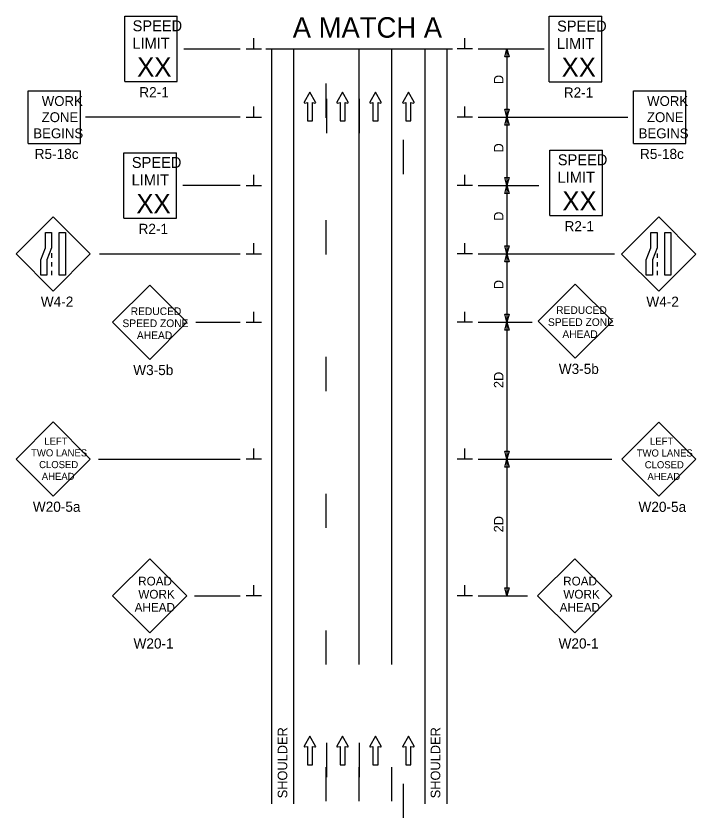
# Model space of a CAD drawing. Extents: x 16512 to 19509, y 5761 to 6974.
# Drawn here: x 17850 to 18347, y 6327 to 6913 of the extents above; entities that cross this region are included whole.
import ezdxf

# ---------------------------------------------------------------- set-up
doc = ezdxf.new("R2010")
doc.units = 0
for name, color, linetype in [('ALI_LEGAL_EX', 7, 'Continuous'), ('MT_SCRATCH_LEVEL_E', 7, 'Continuous'), ('PAVT_EDGE_EX', 7, 'Continuous'), ('TRAFFIC_SIGNS_PR', 7, 'Continuous'), ('TYPICAL_TEXT_DIMEN_PR', 7, 'Continuous')]:
    doc.layers.add(name, color=color, linetype=linetype)

msp = doc.modelspace()

# ---------------------------------------------------------------- linework, layer by layer
at = {"layer": 'ALI_LEGAL_EX'}
for p, q in [((18101.18, 6438.7), (18101.18, 6889.05)), ((18125.18, 6438.7), (18125.18, 6889.05))]:
    msp.add_line(p, q, dxfattribs=at)
for points in [[(18077.18, 6838.7), (18077.18, 6863.7)], [(18101.18, 6838.7), (18101.18, 6863.7)], [(18125.18, 6838.7), (18125.18, 6863.7)], [(18077.28, 6852.4), (18077.28, 6827.4)], [(18101.28, 6852.4), (18101.28, 6827.4)], [(18133.42, 6822.52), (18133.42, 6797.52)], [(18077.18, 6738.7), (18077.18, 6763.7)], [(18101.18, 6738.7), (18101.18, 6763.7)], [(18125.18, 6738.7), (18125.18, 6763.7)], [(18077.18, 6638.7), (18077.18, 6663.7)], [(18101.18, 6638.7), (18101.18, 6663.7)], [(18125.18, 6638.7), (18125.18, 6663.7)], [(18077.18, 6538.7), (18077.18, 6563.7)], [(18101.18, 6538.7), (18101.18, 6563.7)], [(18125.18, 6538.7), (18125.18, 6563.7)], [(18077.18, 6438.7), (18077.18, 6463.7)], [(18101.18, 6438.7), (18101.18, 6463.7)], [(18125.18, 6438.7), (18125.18, 6463.7)], [(18077.28, 6381.39), (18077.28, 6356.39)], [(18101.28, 6381.39), (18101.28, 6356.39)], [(18077.18, 6338.7), (18077.18, 6363.7)], [(18101.18, 6338.7), (18101.18, 6363.7)], [(18125.18, 6338.7), (18125.18, 6363.7)], [(18133.42, 6351.51), (18133.42, 6326.51)]]:
    msp.add_lwpolyline(points, dxfattribs=at)
at = {"layer": 'MT_SCRATCH_LEVEL_E'}
for p, q in [((18065.19, 6857.36), (18061.08, 6850.12)), ((18069.34, 6850.12), (18065.19, 6857.36)), ((18089.05, 6857.36), (18084.94, 6850.12)), ((18093.19, 6850.12), (18089.05, 6857.36)), ((18113.1, 6857.36), (18108.99, 6850.12)), ((18117.25, 6850.12), (18113.1, 6857.36)), ((18137.15, 6857.36), (18133.04, 6850.12)), ((18137.15, 6857.36), (18133.04, 6850.12)), ((18141.3, 6850.12), (18137.15, 6857.36)), ((18141.3, 6850.12), (18137.15, 6857.36)), ((18061.57, 6849.44), (18063.34, 6849.75)), ((18063.34, 6849.75), (18063.34, 6836.5)), ((18067.08, 6836.5), (18067.08, 6849.75)), ((18067.08, 6849.75), (18068.86, 6849.44)), ((18085.42, 6849.44), (18087.19, 6849.75)), ((18087.19, 6849.75), (18087.19, 6836.5)), ((18090.94, 6836.5), (18090.94, 6849.75)), ((18090.94, 6849.75), (18092.71, 6849.44)), ((18109.47, 6849.44), (18111.25, 6849.75)), ((18111.25, 6849.75), (18111.25, 6836.5)), ((18114.99, 6836.5), (18114.99, 6849.75)), ((18114.99, 6849.75), (18116.77, 6849.44)), ((18133.52, 6849.44), (18135.3, 6849.76)), ((18133.52, 6849.44), (18135.3, 6849.76)), ((18135.3, 6849.76), (18135.3, 6836.5)), ((18135.3, 6849.76), (18135.3, 6836.5)), ((18139.04, 6836.5), (18139.04, 6849.76)), ((18139.04, 6849.76), (18140.82, 6849.44)), ((18139.04, 6836.5), (18139.04, 6849.76)), ((18139.04, 6849.76), (18140.82, 6849.44)), ((18063.34, 6836.5), (18067.08, 6836.5)), ((18087.19, 6836.5), (18090.94, 6836.5)), ((18111.25, 6836.5), (18114.99, 6836.5)), ((18135.3, 6836.5), (18139.04, 6836.5)), ((18135.3, 6836.5), (18139.04, 6836.5)), ((18065.19, 6386.35), (18061.08, 6379.11)), ((18069.34, 6379.11), (18065.19, 6386.35)), ((18089.05, 6386.35), (18084.94, 6379.11)), ((18093.19, 6379.11), (18089.05, 6386.35)), ((18113.1, 6386.35), (18108.99, 6379.11)), ((18117.25, 6379.11), (18113.1, 6386.35)), ((18137.15, 6386.35), (18133.04, 6379.11)), ((18137.15, 6386.35), (18133.04, 6379.11)), ((18141.3, 6379.11), (18137.15, 6386.35)), ((18141.3, 6379.11), (18137.15, 6386.35)), ((18061.57, 6378.43), (18063.34, 6378.74)), ((18063.34, 6378.74), (18063.34, 6365.49)), ((18067.08, 6365.49), (18067.08, 6378.74)), ((18067.08, 6378.74), (18068.86, 6378.43)), ((18085.42, 6378.43), (18087.19, 6378.74)), ((18087.19, 6378.74), (18087.19, 6365.49)), ((18090.94, 6365.49), (18090.94, 6378.74)), ((18090.94, 6378.74), (18092.71, 6378.43)), ((18109.47, 6378.43), (18111.25, 6378.74)), ((18111.25, 6378.74), (18111.25, 6365.49)), ((18114.99, 6365.49), (18114.99, 6378.74)), ((18114.99, 6378.74), (18116.77, 6378.43)), ((18133.52, 6378.43), (18135.3, 6378.74)), ((18133.52, 6378.43), (18135.3, 6378.74)), ((18135.3, 6378.74), (18135.3, 6365.49)), ((18135.3, 6378.74), (18135.3, 6365.49)), ((18139.04, 6365.49), (18139.04, 6378.74)), ((18139.04, 6378.74), (18140.82, 6378.43)), ((18139.04, 6365.49), (18139.04, 6378.74)), ((18139.04, 6378.74), (18140.82, 6378.43)), ((18063.34, 6365.49), (18067.08, 6365.49)), ((18087.19, 6365.49), (18090.94, 6365.49)), ((18111.25, 6365.49), (18114.99, 6365.49)), ((18135.3, 6365.49), (18139.04, 6365.49)), ((18135.3, 6365.49), (18139.04, 6365.49))]:
    msp.add_line(p, q, dxfattribs=at)
for centre, start, end in [((18061.49, 6849.9), 150.42484, 279.96381), ((18068.93, 6849.9), 260.03619, 29.77312), ((18085.34, 6849.9), 150.42484, 279.96381), ((18092.78, 6849.9), 260.03619, 29.77312), ((18109.4, 6849.9), 150.42484, 279.96381), ((18116.84, 6849.9), 260.03619, 29.77312), ((18133.45, 6849.9), 150.42484, 279.96381), ((18133.45, 6849.9), 150.42484, 279.96381), ((18140.89, 6849.9), 260.03619, 29.77312), ((18140.89, 6849.9), 260.03619, 29.77312), ((18061.49, 6378.89), 150.42484, 279.96381), ((18068.93, 6378.89), 260.03619, 29.77312), ((18085.34, 6378.89), 150.42484, 279.96381), ((18092.78, 6378.89), 260.03619, 29.77312), ((18109.4, 6378.89), 150.42484, 279.96381), ((18116.84, 6378.89), 260.03619, 29.77312), ((18133.45, 6378.89), 150.42484, 279.96381), ((18133.45, 6378.89), 150.42484, 279.96381), ((18140.89, 6378.89), 260.03619, 29.77312), ((18140.89, 6378.89), 260.03619, 29.77312)]:
    msp.add_arc(centre, 0.463, start, end, dxfattribs=at)
at = {"layer": 'PAVT_EDGE_EX'}
for p, q in [((18037.18, 6889.05), (18037.18, 6336.88)), ((18053.18, 6889.05), (18053.18, 6336.88)), ((18149.18, 6889.05), (18149.18, 6336.88)), ((18165.18, 6889.05), (18165.18, 6336.88))]:
    msp.add_line(p, q, dxfattribs=at)
at = {"layer": 'TRAFFIC_SIGNS_PR'}
for p, q in [((17929.75, 6913.08), (17968.15, 6913.08)), ((17929.75, 6865.08), (17929.75, 6913.08)), ((17968.15, 6865.08), (17968.15, 6913.08)), ((18240.14, 6912.88), (18278.54, 6912.88)), ((18240.14, 6864.88), (18240.14, 6912.88)), ((18278.54, 6864.88), (18278.54, 6912.88)), ((17929.75, 6865.08), (17968.15, 6865.08)), ((18240.14, 6864.88), (18278.54, 6864.88)), ((17859.12, 6819.94), (17859.12, 6858.34)), ((17859.12, 6858.34), (17897.52, 6858.34)), ((17897.52, 6819.94), (17897.52, 6858.34)), ((18301.75, 6819.94), (18301.75, 6858.34)), ((18301.75, 6858.34), (18340.15, 6858.34)), ((18340.15, 6819.94), (18340.15, 6858.34)), ((17859.12, 6819.94), (17897.52, 6819.94)), ((18301.75, 6819.94), (18340.15, 6819.94)), ((17929.2, 6813.12), (17967.6, 6813.12)), ((17929.2, 6765.12), (17929.2, 6813.12)), ((17967.6, 6765.12), (17967.6, 6813.12)), ((18240.67, 6815.09), (18279.07, 6815.09)), ((18240.67, 6767.09), (18240.67, 6815.09)), ((18279.07, 6767.09), (18279.07, 6815.09)), ((17877.45, 6766.18), (17850.3, 6739.03)), ((17904.6, 6739.03), (17877.45, 6766.18)), ((17929.2, 6765.12), (17967.6, 6765.12)), ((18240.67, 6767.09), (18279.07, 6767.09)), ((18320.24, 6766.15), (18293.08, 6739)), ((18347.39, 6739), (18320.24, 6766.15)), ((17850.3, 6739.03), (17877.45, 6711.88)), ((17876.2, 6739.52), (17876.2, 6736.32)), ((17877.45, 6711.88), (17904.6, 6739.03)), ((18293.08, 6739), (18320.24, 6711.84)), ((18318.99, 6739.49), (18318.99, 6736.29)), ((18320.24, 6711.84), (18347.39, 6739)), ((17876.2, 6733.12), (17876.2, 6729.92)), ((18318.99, 6733.09), (18318.99, 6729.89)), ((17876.2, 6726.72), (17876.2, 6723.52)), ((18318.99, 6726.69), (18318.99, 6723.49)), ((18259.2, 6717.02), (18232.04, 6689.87)), ((18286.35, 6689.87), (18259.2, 6717.02)), ((17948.05, 6716.19), (17920.9, 6689.04)), ((17975.21, 6689.04), (17948.05, 6716.19)), ((17920.9, 6689.04), (17948.05, 6661.89)), ((17948.05, 6661.89), (17975.21, 6689.04)), ((18232.04, 6689.87), (18259.2, 6662.72)), ((18259.2, 6662.72), (18286.35, 6689.87)), ((17877.44, 6616.2), (17850.29, 6589.05)), ((17904.6, 6589.05), (17877.44, 6616.2)), ((18320.31, 6616.1), (18293.16, 6588.95)), ((18347.47, 6588.95), (18320.31, 6616.1)), ((17850.29, 6589.05), (17877.44, 6561.9)), ((17877.44, 6561.9), (17904.6, 6589.05)), ((18293.16, 6588.95), (18320.31, 6561.8)), ((18320.31, 6561.8), (18347.47, 6588.95)), ((17948.05, 6516.17), (17920.9, 6489.01)), ((17975.21, 6489.01), (17948.05, 6516.17)), ((18258.83, 6516.17), (18231.67, 6489.01)), ((18285.98, 6489.01), (18258.83, 6516.17)), ((17920.9, 6489.01), (17948.05, 6461.86)), ((17948.05, 6461.86), (17975.21, 6489.01)), ((18231.67, 6489.01), (18258.83, 6461.86)), ((18258.83, 6461.86), (18285.98, 6489.01))]:
    msp.add_line(p, q, dxfattribs=at)
for points in [[(17876.2, 6754.77), (17876.2, 6743.59), (17872.86, 6734.7), (17872.86, 6723.52), (17868.36, 6723.52), (17868.36, 6734.7), (17871.71, 6743.59), (17871.71, 6754.77)], [(17886.34, 6754.77), (17886.34, 6723.52), (17881.85, 6723.52), (17881.85, 6754.77)], [(18318.99, 6754.73), (18318.99, 6743.55), (18315.64, 6734.67), (18315.64, 6723.49), (18311.15, 6723.49), (18311.15, 6734.67), (18314.49, 6743.55), (18314.49, 6754.73)], [(18329.12, 6754.73), (18329.12, 6723.49), (18324.63, 6723.49), (18324.63, 6754.73)]]:
    msp.add_lwpolyline(points, close=True, dxfattribs=at)
at = {"layer": 'TYPICAL_TEXT_DIMEN_PR'}
for p, q in [((18024.15, 6889.05), (18024.15, 6896.83)), ((18178.4, 6889.05), (18178.4, 6896.83)), ((17973.04, 6889.05), (18014.28, 6889.05)), ((18018.53, 6889.05), (18029.78, 6889.05)), ((18032.85, 6889.05), (18169.5, 6889.05)), ((18184.03, 6889.05), (18172.78, 6889.05)), ((18188.28, 6889.05), (18236.42, 6889.05)), ((18207.71, 6883.19), (18209.28, 6889.05)), ((18209.28, 6889.05), (18209.28, 6839.05)), ((18209.28, 6889.05), (18210.85, 6883.19)), ((18209.28, 6883.19), (18207.71, 6883.19)), ((18210.85, 6883.19), (18209.28, 6883.19)), ((18024.15, 6839.05), (18024.15, 6846.83)), ((18178.4, 6839.05), (18178.4, 6846.83)), ((18209.28, 6839.05), (18207.71, 6844.91)), ((18207.71, 6844.91), (18209.28, 6844.91)), ((18209.28, 6844.91), (18210.85, 6844.91)), ((18210.85, 6844.91), (18209.28, 6839.05)), ((18014.28, 6839.05), (17901.17, 6839.05)), ((18018.53, 6839.05), (18029.78, 6839.05)), ((18184.03, 6839.05), (18172.78, 6839.05)), ((18188.28, 6839.05), (18297.6, 6839.05)), ((18207.71, 6833.19), (18209.28, 6839.05)), ((18209.28, 6839.05), (18210.85, 6833.19)), ((18209.28, 6839.05), (18209.28, 6789.05)), ((18209.28, 6833.19), (18207.71, 6833.19)), ((18210.85, 6833.19), (18209.28, 6833.19)), ((18024.15, 6789.05), (18024.15, 6796.83)), ((18178.4, 6789.05), (18178.4, 6796.83)), ((18209.28, 6789.05), (18207.71, 6794.91)), ((18207.71, 6794.91), (18209.28, 6794.91)), ((18209.28, 6794.91), (18210.85, 6794.91)), ((18210.85, 6794.91), (18209.28, 6789.05)), ((18014.28, 6789.05), (17972.22, 6789.05)), ((18018.53, 6789.05), (18029.78, 6789.05)), ((18184.03, 6789.05), (18172.78, 6789.05)), ((18188.28, 6789.05), (18232.62, 6789.05)), ((18207.71, 6783.19), (18209.28, 6789.05)), ((18209.28, 6789.05), (18209.28, 6739.05)), ((18209.28, 6789.05), (18210.85, 6783.19)), ((18209.28, 6783.19), (18207.71, 6783.19)), ((18210.85, 6783.19), (18209.28, 6783.19)), ((18024.15, 6739.05), (18024.15, 6746.83)), ((18178.4, 6739.05), (18178.4, 6746.83)), ((18209.28, 6739.05), (18207.71, 6744.91)), ((18207.71, 6744.91), (18209.28, 6744.91)), ((18209.28, 6744.91), (18210.85, 6744.91)), ((18210.85, 6744.91), (18209.28, 6739.05)), ((17911.24, 6739.05), (18014.28, 6739.05)), ((18018.53, 6739.05), (18029.78, 6739.05)), ((18184.03, 6739.05), (18172.78, 6739.05)), ((18188.28, 6739.05), (18287.94, 6739.05)), ((18207.71, 6733.19), (18209.28, 6739.05)), ((18209.28, 6739.05), (18209.28, 6689.05)), ((18209.28, 6739.05), (18210.85, 6733.19)), ((18209.28, 6733.19), (18207.71, 6733.19)), ((18210.85, 6733.19), (18209.28, 6733.19)), ((18024.15, 6689.05), (18024.15, 6696.83)), ((18178.4, 6689.05), (18178.4, 6696.83)), ((18209.28, 6689.05), (18207.71, 6694.91)), ((18207.71, 6694.91), (18209.28, 6694.91)), ((18209.28, 6694.91), (18210.85, 6694.91)), ((18210.85, 6694.91), (18209.28, 6689.05)), ((17981.76, 6689.05), (18014.28, 6689.05)), ((18018.53, 6689.05), (18029.78, 6689.05)), ((18184.03, 6689.05), (18172.78, 6689.05)), ((18188.28, 6689.05), (18227.73, 6689.05)), ((18207.71, 6683.19), (18209.28, 6689.05)), ((18207.71, 6683.19), (18209.28, 6689.05)), ((18209.28, 6689.05), (18209.28, 6589.05)), ((18209.28, 6689.05), (18210.85, 6683.19)), ((18209.28, 6689.05), (18210.85, 6683.19)), ((18209.28, 6689.05), (18209.28, 6589.05)), ((18209.28, 6683.19), (18207.71, 6683.19)), ((18209.28, 6683.19), (18207.71, 6683.19)), ((18210.85, 6683.19), (18209.28, 6683.19)), ((18210.85, 6683.19), (18209.28, 6683.19)), ((18024.15, 6589.05), (18024.15, 6596.83)), ((18024.15, 6589.05), (18024.15, 6596.83)), ((18178.4, 6589.05), (18178.4, 6596.83)), ((18178.4, 6589.05), (18178.4, 6596.83)), ((18209.28, 6589.05), (18207.71, 6594.91)), ((18207.71, 6594.91), (18209.28, 6594.91)), ((18209.28, 6594.91), (18210.85, 6594.91)), ((18210.85, 6594.91), (18209.28, 6589.05)), ((17910.57, 6589.05), (18014.28, 6589.05)), ((18029.78, 6589.05), (18018.53, 6589.05)), ((18029.78, 6589.05), (18018.53, 6589.05)), ((18184.03, 6589.05), (18172.78, 6589.05)), ((18184.03, 6589.05), (18172.78, 6589.05)), ((18188.28, 6589.05), (18286.07, 6589.05)), ((18188.28, 6589.05), (18214.28, 6589.05)), ((18207.71, 6583.19), (18209.28, 6589.05)), ((18209.28, 6589.05), (18209.28, 6489.05)), ((18209.28, 6589.05), (18210.85, 6583.19)), ((18209.28, 6583.19), (18207.71, 6583.19)), ((18210.85, 6583.19), (18209.28, 6583.19)), ((18024.15, 6489.05), (18024.15, 6496.83)), ((18178.4, 6489.05), (18178.4, 6496.83)), ((18209.28, 6489.05), (18207.71, 6494.91)), ((18207.71, 6494.91), (18209.28, 6494.91)), ((18209.28, 6494.91), (18210.85, 6494.91)), ((18210.85, 6494.91), (18209.28, 6489.05)), ((17980.88, 6489.05), (18014.28, 6489.05)), ((18029.78, 6489.05), (18018.53, 6489.05)), ((18184.03, 6489.05), (18172.78, 6489.05)), ((18188.28, 6489.05), (18224.28, 6489.05))]:
    msp.add_line(p, q, dxfattribs=at)

# ---------------------------------------------------------------- texts
at = {"layer": 'TRAFFIC_SIGNS_PR'}
for s, height, p in [('SPEED', 8, (17935.51, 6901.94)), ('SPEED', 8, (18245.91, 6901.74)), ('LIMIT', 8, (17935.35, 6889.14)), ('LIMIT', 8, (18245.75, 6888.94)), ('XX', 14.031, (17938.86, 6868.84)), ('XX', 14.031, (18249.26, 6868.64)), ('R2-1', 7.44, (17940.42, 6853.64)), ('R2-1', 7.44, (18250.82, 6853.44)), ('WORK', 7.217, (17869.11, 6847.3)), ('WORK', 7.217, (18311.75, 6847.3)), ('ZONE', 7.217, (17869, 6835.49)), ('ZONE', 7.217, (18311.63, 6835.49)), ('BEGINS', 7.217, (17862.93, 6823.68)), ('BEGINS', 7.217, (18305.56, 6823.68)), ('R5-18c', 7.44, (17863.93, 6808.5)), ('R5-18c', 7.44, (18306.56, 6808.5)), ('SPEED', 8, (17934.96, 6801.98)), ('SPEED', 8, (18246.44, 6803.95)), ('LIMIT', 8, (18246.28, 6791.15)), ('LIMIT', 8, (17934.8, 6789.18)), ('XX', 14.031, (17938.31, 6768.87)), ('XX', 14.031, (18249.78, 6770.85)), ('R2-1', 7.44, (18251.35, 6755.65)), ('R2-1', 7.44, (17939.87, 6753.68)), ('W4-2', 7.44, (17868.41, 6700.44)), ('W4-2', 7.44, (18311.19, 6700.4)), ('REDUCED', 5.6, (17934.11, 6694.35)), ('REDUCED', 5.6, (18245.25, 6695.18)), ('SPEED ZONE', 5.6, (17928.1, 6685.55)), ('SPEED ZONE', 5.6, (18239.25, 6686.38)), ('AHEAD', 5.6, (17938.67, 6676.75)), ('AHEAD', 5.6, (18249.81, 6677.58)), ('W3-5b', 7.44, (17936.01, 6650.45)), ('W3-5b', 7.44, (18247.15, 6651.28)), ('LEFT', 5.2, (17870.98, 6599.58)), ('LEFT', 5.2, (18313.85, 6599.48)), ('TWO LANES', 5.2, (17861.31, 6590.98)), ('TWO LANES', 5.2, (18304.17, 6590.88)), ('CLOSED', 5.2, (17867.16, 6582.38)), ('CLOSED', 5.2, (18310.03, 6582.28)), ('AHEAD', 5.2, (17869.1, 6573.78)), ('AHEAD', 5.2, (18311.97, 6573.68)), ('W20-5a', 7.44, (17862.58, 6550.46)), ('W20-5a', 7.44, (18305.45, 6550.36)), ('ROAD', 6.4, (17939.59, 6496.55)), ('ROAD', 6.4, (18250.37, 6496.55)), ('WORK', 6.4, (17939.7, 6486.95)), ('WORK', 6.4, (18250.48, 6486.95)), ('AHEAD', 6.4, (17937.01, 6477.35)), ('AHEAD', 6.4, (18247.79, 6477.35)), ('W20-1', 7.44, (17936.22, 6450.42)), ('W20-1', 7.44, (18247, 6450.42))]:
    msp.add_text(s, height=height, dxfattribs=at).set_placement(p)
at = {"layer": 'TYPICAL_TEXT_DIMEN_PR'}
msp.add_text('A MATCH A', height=15, dxfattribs=at).set_placement((18052.6, 6897.23))
for s, p in [('D', (18206.72, 6863.27)), ('D', (18206.72, 6813.27)), ('D', (18206.72, 6763.27)), ('D', (18206.72, 6713.27)), ('2D', (18206.72, 6640.94)), ('2D', (18206.72, 6535.41)), ('SHOULDER', (18048.62, 6340.9)), ('SHOULDER', (18160.48, 6340.9))]:
    msp.add_text(s, height=7, rotation=90, dxfattribs=at).set_placement(p)

doc.saveas('drawing.dxf')
